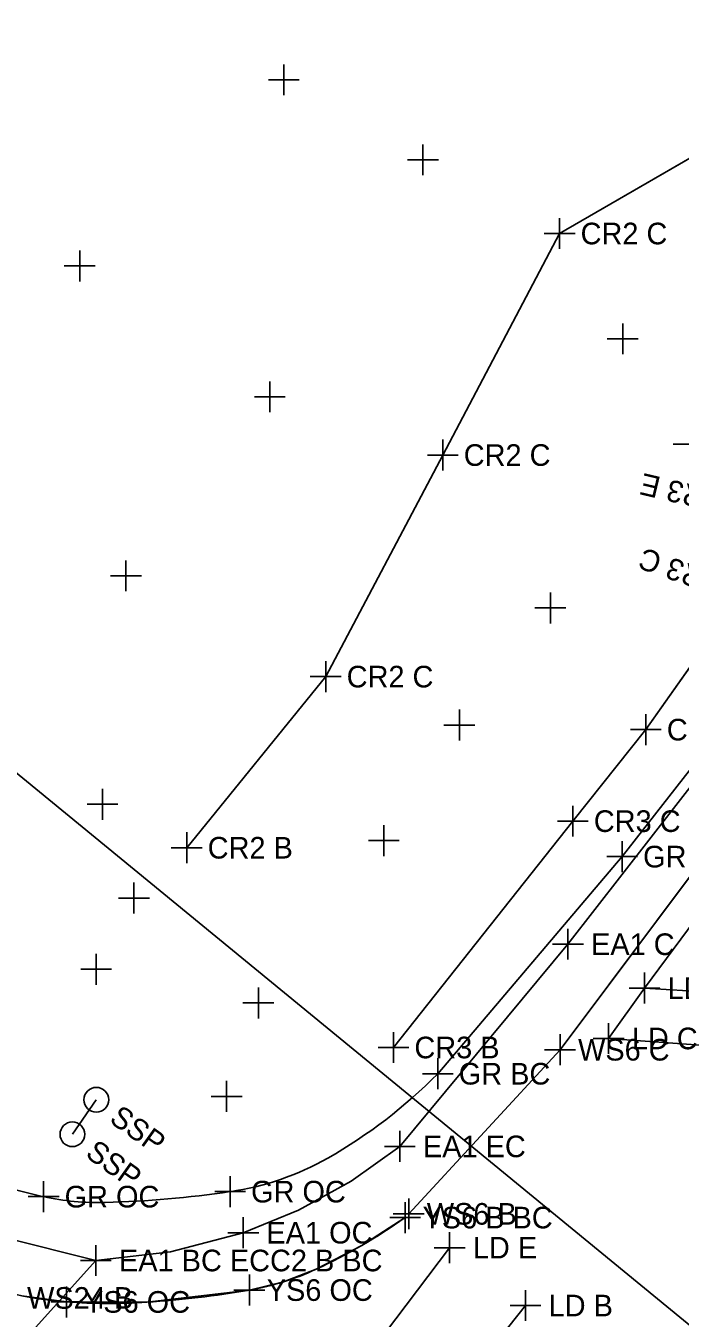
# Model space of a CAD drawing. Extents: x 1324236 to 1326110, y 459090 to 460782.
# Drawn here: x 1324997.6 to 1325040, y 459917.7 to 460001.4 of the extents above; entities that cross this region are included whole.
import ezdxf

# ---------------------------------------------------------------- set-up
doc = ezdxf.new("R2010")
doc.units = 0
for name, color, linetype in [('DR_X_Ditch', 7, 'Continuous'), ('DT_X_Contour_Minor', 7, 'Continuous'), ('DT_X_Island', 7, 'Continuous'), ('DV_X_Property_Line', 7, 'Continuous'), ('E-RW-ODOT', 7, 'Continuous'), ('PM_X_Edge_Line', 7, 'Continuous'), ('PM_X_Misc', 7, 'Continuous'), ('PV_X_Shoulder', 7, 'Continuous'), ('RW_X_CL', 7, 'Continuous'), ('RW_X_Esmt_SH', 7, 'Continuous'), ('RW_X_Fee_RW', 7, 'Continuous')]:
    doc.layers.add(name, color=color, linetype=linetype)

msp = doc.modelspace()

# ---------------------------------------------------------------- linework, layer by layer
at = {"layer": 'DR_X_Ditch'}
for points in [[(1325022.412, 459924.498), (1325032.208, 459935.122), (1325047.842, 459955.983), (1325054.62, 459965.363)], [(1325022.18, 459924.256), (1325019.374, 459922.458), (1325016.419, 459920.919), (1325016.419, 459920.919), (1325014.299, 459920.098), (1325012.09, 459919.563), (1325012.09, 459919.563), (1325005.452, 459918.775), (1325005.452, 459918.775), (1325000.258, 459918.796), (1325000.258, 459918.796), (1324997.345, 459919.198)]]:
    msp.add_lwpolyline(points, dxfattribs=at)
at = {"layer": 'DT_X_Contour_Minor'}
msp.add_line((1325000.629, 459929.649), (1325002.179, 459931.883), dxfattribs=at)
for centre in [(1325002.179, 459931.883), (1325000.629, 459929.649)]:
    msp.add_circle(centre, 0.8, dxfattribs=at)
at = {"layer": 'DT_X_Island'}
for p, q in [((1325032.183, 459987.963), (1325044.358, 459995.008)), ((1325024.616, 459973.622), (1325032.183, 459987.963)), ((1325017.034, 459959.277), (1325024.616, 459973.622)), ((1325037.766, 459955.844), (1325043.971, 459964.659)), ((1325008.034, 459948.199), (1325017.034, 459959.277)), ((1325033.04, 459949.922), (1325037.766, 459955.844)), ((1325021.42, 459935.267), (1325033.04, 459949.922))]:
    msp.add_line(p, q, dxfattribs=at)
for points in [[(1325008.034, 459948.199), (1325017.034, 459959.277), (1325024.616, 459973.622), (1325032.183, 459987.963), (1325044.358, 459995.008)], [(1325021.42, 459935.267), (1325033.04, 459949.922), (1325037.766, 459955.844), (1325043.971, 459964.659), (1325044.121, 459970.199)]]:
    msp.add_lwpolyline(points, dxfattribs=at)
at = {"layer": 'DV_X_Property_Line'}
for p, q in [((1325032.718, 459940.954), (1325032.718, 459942.954)), ((1325031.718, 459941.954), (1325033.718, 459941.954)), ((1325021.831, 459927.865), (1325021.831, 459929.865)), ((1325020.831, 459928.865), (1325022.831, 459928.865)), ((1325011.694, 459922.277), (1325011.694, 459924.277)), ((1325010.694, 459923.277), (1325012.694, 459923.277)), ((1325002.148, 459920.478), (1325002.148, 459922.478)), ((1325001.148, 459921.478), (1325003.148, 459921.478))]:
    msp.add_line(p, q, dxfattribs=at)
at = {"layer": 'E-RW-ODOT'}
msp.add_line((1324967.69, 459977.085), (1325119.343, 459852.693), dxfattribs=at)
at = {"layer": 'PM_X_Edge_Line'}
for p, q in [((1325032.208, 459935.122), (1325047.842, 459955.983)), ((1325022.412, 459924.498), (1325032.208, 459935.122))]:
    msp.add_line(p, q, dxfattribs=at)
for centre, radius, start, end in [((1325000.743, 459954.621), 37.17, 294.9438, 305.22064), ((1325009.142, 459936.563), 17.254, 279.83636, 294.9438), ((1325001.928, 459941.646), 22.91, 251.10433, 265.82065), ((1325001.407, 459981.18), 62.536, 273.70896, 279.83636), ((1325003.01, 459956.452), 37.756, 265.82065, 273.70896)]:
    msp.add_arc(centre, radius, start, end, dxfattribs=at)
at = {"layer": 'PM_X_Misc'}
for p, q in [((1325045.516, 459959.514), (1325036.23, 459947.624)), ((1325036.23, 459947.624), (1325024.292, 459933.569))]:
    msp.add_line(p, q, dxfattribs=at)
for centre, radius, start, end in [((1325001.036, 459956.53), 32.681, 299.58359, 315.36532), ((1325006.691, 459961.827), 37.074, 246.67003, 257.65984), ((1325008.2, 459943.911), 18.171, 278.36439, 299.58359), ((1325000.924, 459993.397), 68.188, 271.53701, 278.36439), ((1325002.308, 459941.794), 16.566, 257.65984, 271.53701)]:
    msp.add_arc(centre, radius, start, end, dxfattribs=at)
at = {"layer": 'PV_X_Shoulder'}
for points in [[(1325002.148, 459921.478), (1324996.212, 459922.965), (1324990.513, 459925.196), (1324985.145, 459928.133), (1324985.145, 459928.133), (1324980.413, 459931.549), (1324976.131, 459935.514), (1324972.361, 459939.969), (1324972.361, 459939.969), (1324953.276, 459964.235), (1324933.65, 459989.173), (1324913.127, 460015.149), (1324893.717, 460039.834), (1324874.175, 460064.594), (1324853.444, 460090.73)], [(1324925.493, 459829.151), (1324945.553, 459855.344), (1324956.783, 459871.328), (1324958.966, 459875.954), (1324960.869, 459880.702), (1324960.869, 459880.702), (1324962.577, 459885.859), (1324963.956, 459891.113), (1324963.956, 459891.113), (1324983.542, 459896.002), (1324987.695, 459905.444), (1325002.148, 459921.478), (1325006.986, 459922.031), (1325011.694, 459923.277), (1325011.694, 459923.277), (1325015.281, 459924.745), (1325018.675, 459926.616), (1325021.831, 459928.865), (1325021.831, 459928.865), (1325032.718, 459941.954), (1325043.207, 459955.431)]]:
    msp.add_lwpolyline(points, dxfattribs=at)
at = {"layer": 'RW_X_CL'}
for p, q in [((1325014.325, 459996.913), (1325014.325, 459998.913)), ((1325013.325, 459997.913), (1325015.325, 459997.913)), ((1325023.33, 459991.735), (1325023.33, 459993.735)), ((1325022.33, 459992.735), (1325024.33, 459992.735)), ((1325032.183, 459986.963), (1325032.183, 459988.963)), ((1325031.183, 459987.963), (1325033.183, 459987.963)), ((1325001.107, 459984.864), (1325001.107, 459986.864)), ((1325000.107, 459985.864), (1325002.107, 459985.864)), ((1325036.264, 459980.147), (1325036.264, 459982.147)), ((1325035.264, 459981.147), (1325037.264, 459981.147)), ((1325013.418, 459976.392), (1325013.418, 459978.392)), ((1325012.418, 459977.392), (1325014.418, 459977.392)), ((1325024.616, 459972.622), (1325024.616, 459974.622)), ((1325039.536, 459974.325), (1325041.536, 459974.325)), ((1325023.616, 459973.622), (1325025.616, 459973.622)), ((1325004.094, 459964.804), (1325004.094, 459966.804)), ((1325003.094, 459965.804), (1325005.094, 459965.804)), ((1325031.583, 459962.724), (1325031.583, 459964.724)), ((1325030.583, 459963.724), (1325032.583, 459963.724)), ((1325017.034, 459958.277), (1325017.034, 459960.277)), ((1325016.034, 459959.277), (1325018.034, 459959.277)), ((1325025.687, 459955.143), (1325025.687, 459957.143)), ((1325037.766, 459954.844), (1325037.766, 459956.844)), ((1325024.687, 459956.143), (1325026.687, 459956.143)), ((1325036.766, 459955.844), (1325038.766, 459955.844)), ((1325002.577, 459950.01), (1325002.577, 459952.01)), ((1325001.577, 459951.01), (1325003.577, 459951.01)), ((1325033.04, 459948.922), (1325033.04, 459950.922)), ((1325032.04, 459949.922), (1325034.04, 459949.922)), ((1325008.034, 459947.199), (1325008.034, 459949.199)), ((1325020.801, 459947.659), (1325020.801, 459949.659)), ((1325019.801, 459948.659), (1325021.801, 459948.659)), ((1325007.034, 459948.199), (1325009.034, 459948.199)), ((1325004.615, 459943.942), (1325004.615, 459945.942)), ((1325003.615, 459944.942), (1325005.615, 459944.942)), ((1325002.172, 459939.328), (1325002.172, 459941.328)), ((1325001.172, 459940.328), (1325003.172, 459940.328)), ((1325012.673, 459937.153), (1325012.673, 459939.153)), ((1325011.673, 459938.153), (1325013.673, 459938.153)), ((1325021.42, 459934.267), (1325021.42, 459936.267)), ((1325032.208, 459934.122), (1325032.208, 459936.122)), ((1325020.42, 459935.267), (1325022.42, 459935.267)), ((1325031.208, 459935.122), (1325033.208, 459935.122)), ((1325010.613, 459931.104), (1325010.613, 459933.104)), ((1325009.613, 459932.104), (1325011.613, 459932.104)), ((1325022.18, 459923.256), (1325022.18, 459925.256)), ((1325022.412, 459923.498), (1325022.412, 459925.498)), ((1325021.18, 459924.256), (1325023.18, 459924.256)), ((1325021.412, 459924.498), (1325023.412, 459924.498)), ((1325000.258, 459917.796), (1325000.258, 459919.796)), ((1325012.09, 459918.563), (1325012.09, 459920.563)), ((1325011.09, 459919.563), (1325013.09, 459919.563)), ((1324999.258, 459918.796), (1325001.258, 459918.796))]:
    msp.add_line(p, q, dxfattribs=at)
at = {"layer": 'RW_X_Esmt_SH'}
for p, q in [((1325036.23, 459946.624), (1325036.23, 459948.624)), ((1325035.23, 459947.624), (1325037.23, 459947.624)), ((1325037.676, 459938.113), (1325037.676, 459940.113)), ((1325036.676, 459939.113), (1325038.676, 459939.113)), ((1325035.356, 459934.853), (1325035.356, 459936.853)), ((1325034.356, 459935.853), (1325036.356, 459935.853)), ((1325024.292, 459932.569), (1325024.292, 459934.569)), ((1325023.292, 459933.569), (1325025.292, 459933.569)), ((1324998.768, 459924.61), (1324998.768, 459926.61)), ((1325010.843, 459924.934), (1325010.843, 459926.934)), ((1325009.843, 459925.934), (1325011.843, 459925.934)), ((1324997.768, 459925.61), (1324999.768, 459925.61)), ((1325025.06, 459921.308), (1325025.06, 459923.308)), ((1325024.06, 459922.308), (1325026.06, 459922.308)), ((1325029.969, 459917.562), (1325029.969, 459919.562)), ((1325028.969, 459918.562), (1325030.969, 459918.562))]:
    msp.add_line(p, q, dxfattribs=at)
at = {"layer": 'RW_X_Fee_RW'}
for p, q in [((1325053.601, 459960.593), (1325037.676, 459939.113)), ((1325037.676, 459939.113), (1325035.356, 459935.853)), ((1325037.676, 459939.113), (1325045.36, 459938.63)), ((1325035.356, 459935.853), (1325043.102, 459935.277)), ((1325017.616, 459912.473), (1325025.06, 459922.308)), ((1325029.969, 459918.562), (1325022.21, 459908.824))]:
    msp.add_line(p, q, dxfattribs=at)

# ---------------------------------------------------------------- texts
at = {"layer": 'DT_X_Contour_Minor'}
for rotation, p in [(324.52612, (1325002.951, 459930.474)), (324.51574, (1325001.4, 459928.239))]:
    msp.add_text('SSP', height=1.4, rotation=rotation, dxfattribs=at).set_placement(p)
at = {"layer": 'DV_X_Property_Line'}
for s, p in [('EA1 C', (1325034.218, 459941.254)), ('EA1 EC', (1325023.331, 459928.165)), ('EA1 OC', (1325013.194, 459922.577)), ('EA1 BC ECC2 B BC', (1325003.648, 459920.778))]:
    msp.add_text(s, height=1.4, dxfattribs=at).set_placement(p)
at = {"layer": 'RW_X_CL'}
for s, p in [('CR2 C', (1325033.54, 459987.263)), ('CR2 C', (1325025.973, 459972.922)), ('CR2 C', (1325018.391, 459958.577)), ('CR3 C', (1325039.123, 459955.144)), ('CR3 C', (1325034.397, 459949.222)), ('CR2 B', (1325009.391, 459947.499)), ('CR3 B', (1325022.777, 459934.567)), ('WS6 C', (1325033.375, 459934.422)), ('YS6 B BC', (1325023.305, 459923.556)), ('WS6 B', (1325023.579, 459923.798)), ('WS24 B', (1324997.694, 459918.353)), ('YS6 OC', (1325013.215, 459918.863)), ('YS6 OC', (1325001.383, 459918.096))]:
    msp.add_text(s, height=1.4, dxfattribs=at).set_placement(p)
for s, rotation, p in [('CR3 E', 166.6663, (1325042.962, 459971.193)), ('CR3 C', 160.41902, (1325042.927, 459965.773))]:
    msp.add_text(s, height=1.4, rotation=rotation, dxfattribs=at).set_placement(p)
at = {"layer": 'RW_X_Esmt_SH'}
for s, p in [('GR C', (1325037.587, 459946.924)), ('LD C LD1 B', (1325039.176, 459938.413)), ('LD C', (1325036.856, 459935.153)), ('GR BC', (1325025.649, 459932.869)), ('GR OC', (1325012.2, 459925.234)), ('GR OC', (1325000.125, 459924.91)), ('LD E', (1325026.56, 459921.608)), ('LD B', (1325031.469, 459917.862))]:
    msp.add_text(s, height=1.4, dxfattribs=at).set_placement(p)

doc.saveas('drawing.dxf')
